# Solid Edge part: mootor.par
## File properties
Author: Indrek
Template: Normal.par
Last saved by: Indrek
Revision: 17
Application: Solid Edge
Density: 2795,000 kg/m^3
Accuracy: 0,990
Material: Aluminum, 7075-T6
Face Style: Aluminum
Fill Style: ANSI38(Aluminum)
Virtual Style: Polished aluminum
Coef. of Thermal Exp: 2.3e-05
Thermal Conductivity: 121.0
Specific Heat: 920.0
Modulus of Elasticity: 71705472800.0
Poission's Ratio: 0.33
Yield Stress: 503317261.0
Ultimate Stress: 572264831.0
Elongation: 0.0
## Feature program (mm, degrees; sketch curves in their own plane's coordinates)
make body feature "unnamed MakeBodyFeature 1"
sketch for "unnamed Cutout 1" plane through (0, 0, 0) normal (0, -1, 0) x-axis (1, 0, 0)
  line (253.2783, -199.2064) -> (-238.0348, -199.2064)
  line (-238.0348, -199.2064) -> (-238.0348, -307.2438)
  line (-238.0348, -307.2438) -> (253.2783, -307.2438)
  line (253.2783, -307.2438) -> (253.2783, -199.2064)
extrude "unnamed Cutout 1" cut finite 1049.3973 symmetric
sketch for "ExtrudedCutout_3" plane through (0, 0, -199.2064) normal (0, 0, -1) x-axis (1, 0, 0)
extrude "ExtrudedCutout_3" cut finite 2 along -normal
sketch for "ExtrudedCutout_5" plane through (0, 0, 0) normal (0, 0, 1) x-axis (1, 0, 0)
extrude "ExtrudedCutout_5" cut finite 596.7341 symmetric
sketch for "ExtrudedCutout_6" plane through (0, 732.4572, 0) normal (0, -1, 0) x-axis (1, 0, 0)
  circle centre (0, 0) radius 100
extrude "ExtrudedCutout_6" cut finite 175.3212 along +normal
sketch for "unnamed RevolvedProtrusion 1" plane through (0, 0, 0) normal (1, 0, 0) x-axis (0, 1, 0)
  line (698.9011, 0) -> (557.1361, 0)
  line (557.1361, 0) -> (557.1361, 100)
  line (557.1361, 100) -> (664.1721, 100)
  line (664.1721, 100) -> (666.8351, 100)
  arc centre (576.2324, 18.6758) radius 121.7476 from (666.8351, 100) to (637.6185, 123.8148) ccw
  arc centre (593.5603, -75.4029) radius 204.0315 from (697.7844, 100) to (637.6185, 123.8148) ccw
  line (697.7844, 100) -> (675.6941, 90.4972)
  arc centre (640.2011, 173.0044) radius 89.8176 from (640.2011, 83.1869) to (675.6941, 90.4972) ccw
  line (640.2011, 83.1869) -> (583.8826, 83.1869)
  arc centre (583.8826, 68.2977) radius 14.8891 from (568.9934, 68.2977) to (583.8826, 83.1869) cw
  line (568.9934, 68.2977) -> (568.9934, 61.9992)
  arc centre (586.1453, 61.9992) radius 17.1518 from (586.1453, 44.8474) to (568.9934, 61.9992) cw
  line (586.1453, 44.8474) -> (597.3737, 44.8474)
  arc centre (597.3737, -56.1879) radius 101.0353 from (650.2841, 29.8855) to (597.3737, 44.8474) ccw
  line (650.2841, 29.8855) -> (698.9011, 0)
revolve "unnamed RevolvedProtrusion 1" add finite 360 deg
lofted protrusion "unnamed LoftedProtrusion 1"
lofted protrusion "unnamed LoftedProtrusion 2"
lofted protrusion "unnamed LoftedProtrusion 3"
lofted protrusion "LoftedProtrusion_10"  StartTangentMagnitude1 = 1; EndTangentMagnitude1 = 1
lofted protrusion "LoftedProtrusion_11"  EndTangentMagnitude1 = 1; StartTangentMagnitude1 = 1
pattern "unnamed Pattern 1" of "unnamed LoftedProtrusion 1", "LoftedProtrusion_11", "unnamed LoftedProtrusion 2", "unnamed LoftedProtrusion 3", "LoftedProtrusion_10"
lofted protrusion "unnamed LoftedProtrusion 4"
lofted protrusion "unnamed LoftedProtrusion 5"
lofted protrusion "unnamed LoftedProtrusion 6"
lofted protrusion "unnamed LoftedProtrusion 7"
lofted protrusion "unnamed LoftedProtrusion 8"
lofted protrusion "unnamed LoftedProtrusion 9"
lofted protrusion "unnamed LoftedProtrusion 10"
lofted protrusion "unnamed LoftedProtrusion 11"
lofted protrusion "unnamed LoftedProtrusion 12"
lofted protrusion "unnamed LoftedProtrusion 13"
lofted protrusion "unnamed LoftedProtrusion 14"
lofted protrusion "unnamed LoftedProtrusion 15"
lofted protrusion "unnamed LoftedProtrusion 16"
lofted protrusion "unnamed LoftedProtrusion 17"
lofted protrusion "unnamed LoftedProtrusion 18"
thinwall "Thinwall_1"  Thickness = 6 mm
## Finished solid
Body 1: solid body, 66 faces, 105 edges, 50 vertices.
  Faces by surface: spline 24, plane 16, torus 12, cylinder 6, cone 4, offset 4
  Edges by curve: intersection 54, circle 22, ellipse 20, spline 8, line 1
Body 2: solid body, 8 faces, 12 edges, 6 vertices.
  Faces by surface: spline 8
  Edges by curve: spline 8, circle 4
Bounding box of the edges (mm; curved faces can reach further): 585.326 x 1435.527 x 576.703, from (-292.6628, -717.7634, -288.3515) to (292.6628, 717.7634, 288.3515).
Cylindrical faces by radius (mm): R38.8474 x1, R44.8474 x1, R83.1869 x1, R89.1869 x1, R94 x1, R100 x1
Conical faces (half-angle, radius in mm at the cone's reference point): 23.2764 deg R100 x1, 23.2764 deg R105.5117 x1, 31.5795 deg R24.774 x1, 31.5795 deg R29.8855 x1
Toroidal faces (ring radius, tube radius in mm): R-75.4029 r198.0315 x1, R-75.4029 r204.0315 x1, R-56.1879 r95.0353 x1, R-56.1879 r101.0353 x1, R18.6758 r121.7476 x1, R18.6758 r127.7476 x1, R61.9992 r17.1518 x1, R61.9992 r23.1518 x1, R68.2977 r14.8891 x1, R68.2977 r20.8891 x1, R173.0044 r83.8176 x1, R173.0044 r89.8176 x1
Planar faces by outward normal: +x 3, +y 1, +z 3, -x 3, -y 2, -z 4
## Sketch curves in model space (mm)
line (15, 687.3678, -100) -> (15, 692.3678, -100)
line (15, 692.3678, -100) -> (0, 692.3678, -100)
line (-15, 692.3678, -100) -> (0, 692.3678, -100)
line (-15, 687.3678, -100) -> (-15, 692.3678, -100)
line (0, 687.3678, -100) -> (-15, 687.3678, -100)
line (0, 687.3678, -100) -> (15, 687.3678, -100)
ellipse centre (-15, 666.8387, -238.3631) radii 3.4561, 1.0162
ellipse centre (15, 666.8387, -238.3631) radii 3.4561, 1.0162
ellipse centre (-8, 629.9932, -238.3631) radii 13.7677, 3.5213
ellipse centre (8, 629.9932, -238.3631) radii 13.7677, 3.5213
ellipse centre (0, 624.283, -238.3631) radii 25.6177, 3.5497
ellipse centre (0, 652.7583, -252.8634) radii 20, 3.9335
ellipse centre (0, 578.6885, -201.4731) radii 50, 12.6116
ellipse centre (0, 543.5322, -109.487) radii 30, 6.9524
circle centre (0, 732.4572, 0) radius 100
line (0, 664.1721, 100) -> (0, 666.8351, 100)
arc centre (0, 576.2324, 18.6758) radius 121.7476 from (0, 666.8351, 100) through (0, 653.154, 113.0449) to (0, 637.6185, 123.8148)
arc centre (0, 593.5603, -75.4029) radius 204.0315 from (0, 697.7844, 100) through (0, 668.6516, 114.3078) to (0, 637.6185, 123.8148)
line (0, 697.7844, 100) -> (0, 675.6941, 90.4972)
arc centre (0, 640.2011, 173.0044) radius 89.8176 from (0, 640.2011, 83.1869) through (0, 658.3201, 85.0334) to (0, 675.6941, 90.4972)
line (0, 640.2011, 83.1869) -> (0, 583.8826, 83.1869)
arc centre (0, 583.8826, 68.2977) radius 14.8891 from (0, 568.9934, 68.2977) through (0, 573.665, 79.1277) to (0, 583.8826, 83.1869)
line (0, 568.9934, 68.2977) -> (0, 568.9934, 61.9992)
arc centre (0, 586.1453, 61.9992) radius 17.1518 from (0, 586.1453, 44.8474) through (0, 573.6695, 50.2289) to (0, 568.9934, 61.9992)
line (0, 586.1453, 44.8474) -> (0, 597.3737, 44.8474)
arc centre (0, 597.3737, -56.1879) radius 101.0353 from (0, 650.2841, 29.8855) through (0, 624.8663, 41.035) to (0, 597.3737, 44.8474)
line (0, 650.2841, 29.8855) -> (0, 698.9011, 0)
line (0, 698.9011, 0) -> (0, 557.1361, 0)
line (0, 557.1361, 0) -> (0, 557.1361, 100)
line (0, 557.1361, 100) -> (0, 664.1721, 100)
arc centre (-13.6069, 0, -18.0737) radius 306.6183 from (0, 0, 288.2425) through (207.9336, 0, 193.9041) to (292.4783, 0, 0)
spline (0, 717.7634, 0) -> (219.6102, 411.5079, 0) -> (292.4783, 0, 0)
spline (0, 0, 288.2425) -> (0, 509.0425, 195.77) -> (0, 717.7634, 0)
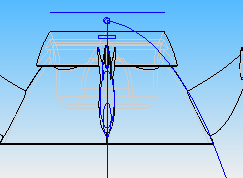
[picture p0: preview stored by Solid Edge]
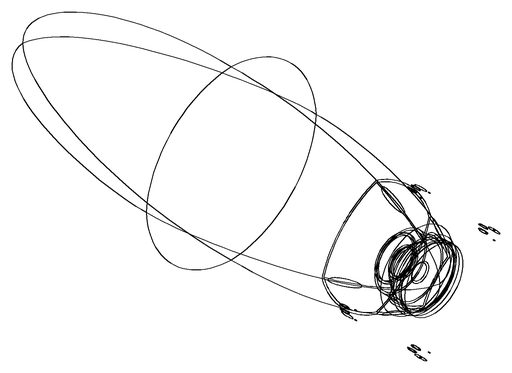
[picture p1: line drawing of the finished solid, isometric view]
